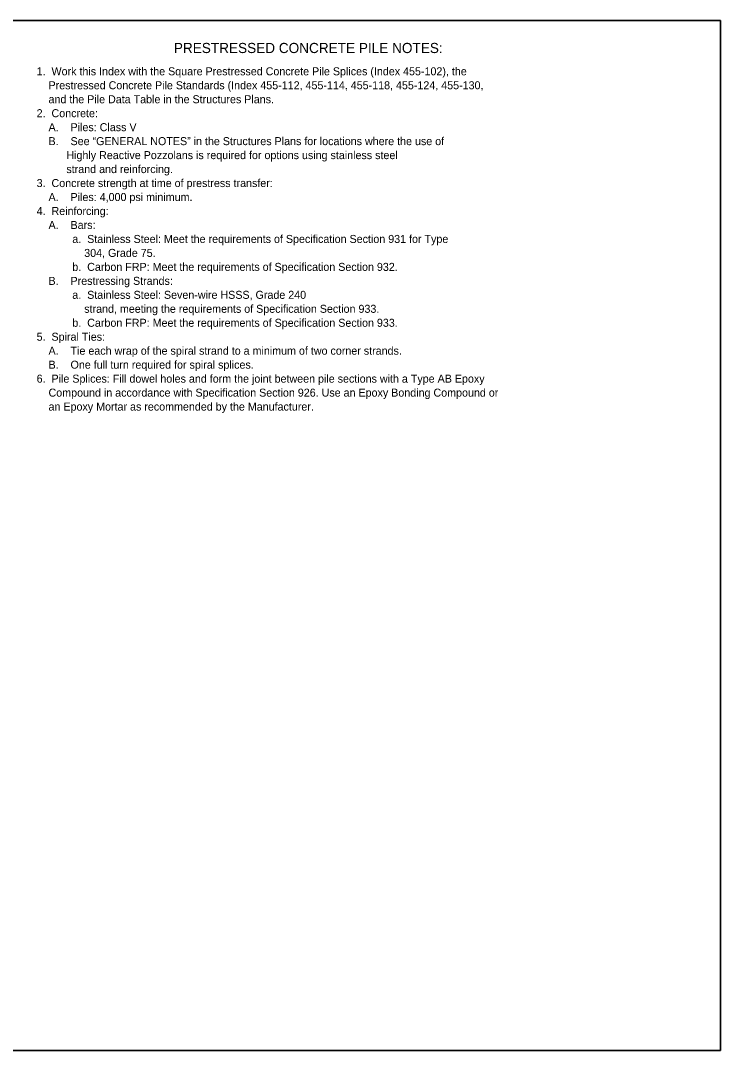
# Model space of a CAD drawing. Extents: x 0 to 20.5, y 0 to 13.
# Drawn here: x 11.71 to 20.53, y 0 to 12.97 of the extents above; entities that cross this region are included whole.
import ezdxf

# ---------------------------------------------------------------- set-up
doc = ezdxf.new("R2010")
doc.units = 0
for name, color, linetype in [('CL_Minor', 7, 'Continuous'), ('Dimension', 7, 'Continuous'), ('Miscellaneous1', 7, 'Continuous'), ('TextStructures', 7, 'Continuous')]:
    doc.layers.add(name, color=color, linetype=linetype)

msp = doc.modelspace()

# ---------------------------------------------------------------- linework, layer by layer
at = {"layer": 'CL_Minor'}
msp.add_lwpolyline([(0, 0), (20.525, 0), (20.525, 12.973), (0, 12.973)], close=True, dxfattribs=at)
at = {"layer": 'Miscellaneous1'}
msp.add_lwpolyline([(0, 12.973), (20.525, 12.973), (20.525, 0), (0, 0)], close=True, dxfattribs=at)

# ---------------------------------------------------------------- texts
at = {"layer": 'Dimension'}
for s, p in [('1.  Work this Index with the Square Prestressed Concrete Pile Splices (Index 455-102), the', (11.914, 12.284)), ('    Prestressed Concrete Pile Standards (Index 455-112, 455-114, 455-118, 455-124, 455-130,', (11.914, 12.108)), ('    and the Pile Data Table in the Structures Plans.', (11.914, 11.932)), ('2.  Concrete: ', (11.914, 11.756)), ('    A.    Piles: Class V', (11.914, 11.58)), ('    B.    See “GENERAL NOTES” in the Structures Plans for locations where the use of', (11.914, 11.404)), ('          Highly Reactive Pozzolans is required for options using stainless steel', (11.914, 11.228)), ('          strand and reinforcing.', (11.914, 11.052)), ('3.  Concrete strength at time of prestress transfer:', (11.914, 10.876)), ('    A.    Piles: 4,000 psi minimum.', (11.914, 10.7)), ('4.  Reinforcing:  ', (11.914, 10.524)), ('    A.    Bars: ', (11.914, 10.348)), ('            a.  Stainless Steel: Meet the requirements of Specification Section 931 for Type', (11.914, 10.172)), ('                304, Grade 75.', (11.914, 9.996)), ('            b.  Carbon FRP: Meet the requirements of Specification Section 932.', (11.914, 9.82)), ('    B.    Prestressing Strands: ', (11.914, 9.644)), ('            a.  Stainless Steel: Seven-wire HSSS, Grade 240', (11.914, 9.468)), ('                strand, meeting the requirements of Specification Section 933.', (11.914, 9.292)), ('            b.  Carbon FRP: Meet the requirements of Specification Section 933.', (11.914, 9.116)), ('5.  Spiral Ties:', (11.914, 8.94)), ('    A.    Tie each wrap of the spiral strand to a minimum of two corner strands.  ', (11.914, 8.764)), ('    B.    One full turn required for spiral splices.', (11.914, 8.588)), ('6.  Pile Splices: Fill dowel holes and form the joint between pile sections with a Type AB Epoxy', (11.914, 8.412)), ('    Compound in accordance with Specification Section 926. Use an Epoxy Bonding Compound or', (11.914, 8.236)), ('    an Epoxy Mortar as recommended by the Manufacturer.', (11.914, 8.06))]:
    msp.add_text(s, height=0.1008, dxfattribs=at).set_placement(p)
at = {"layer": 'TextStructures'}
msp.add_text('PRESTRESSED CONCRETE PILE NOTES:', height=0.128, dxfattribs=at).set_placement((13.642, 12.564))

doc.saveas('drawing.dxf')
